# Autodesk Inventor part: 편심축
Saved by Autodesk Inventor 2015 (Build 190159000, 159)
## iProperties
Created: 2025-08
Part Number: 편심축
Material: 일반
Document SubType Name: Modeling
Designer: USER
Density: 1 g/cm^3
Appearance: 기본값
Author: jhkim
Creation Date: 2025-08-05
Sending System: Autodesk Inventor 2026
Preprocessor: ST-DEVELOPER v20.1
Author: USER
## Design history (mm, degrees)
node "편심축1"
node "솔리드1"
node "기준1"
